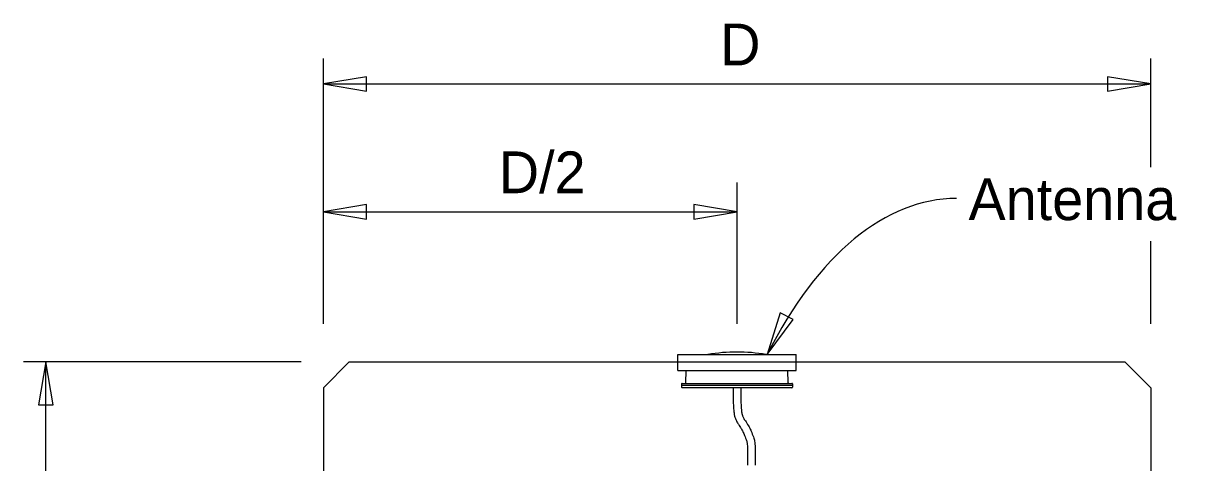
# Model space of a CAD drawing. Extents: x 0 to 36.1, y -3.7 to 15.
# Drawn here: x 1.568 to 4.42, y 8.036 to 9.096 of the extents above; entities that cross this region are included whole.
import ezdxf

# ---------------------------------------------------------------- set-up
doc = ezdxf.new("R2010")
doc.units = 0
for name, color, linetype in [('Dimension', 7, 'Continuous'), ('Leader', 7, 'Continuous'), ('Miscellaneous', 7, 'Continuous'), ('PileConc', 7, 'Continuous'), ('TextStructures', 7, 'Continuous')]:
    doc.layers.add(name, color=color, linetype=linetype)

msp = doc.modelspace()

# ---------------------------------------------------------------- linework, layer by layer
at = {"layer": 'Dimension'}
for p, q in [((2.293, 8.3704), (2.293, 9.0116)), ((4.293, 8.7487), (4.293, 9.0116)), ((2.293, 8.9498), (4.293, 8.9498)), ((3.293, 8.3704), (3.293, 8.7119)), ((2.293, 8.641), (3.293, 8.641)), ((4.293, 8.3704), (4.293, 8.5702)), ((2.2394, 8.2786), (1.5682, 8.2786)), ((1.6218, 6.2786), (1.6218, 8.2786))]:
    msp.add_line(p, q, dxfattribs=at)
for points in [[(2.293, 8.9498), (2.3972, 8.9321), (2.3972, 8.9674)], [(4.293, 8.9498), (4.1889, 8.9674), (4.1889, 8.9321)], [(2.293, 8.641), (2.3972, 8.6233), (2.3972, 8.6586)], [(3.293, 8.641), (3.1889, 8.6586), (3.1889, 8.6233)], [(3.3658, 8.2961), (3.4285, 8.3811), (3.397, 8.397)], [(1.6218, 8.2786), (1.6042, 8.1745), (1.6395, 8.1745)]]:
    msp.add_lwpolyline(points, close=True, dxfattribs=at)
at = {"layer": 'Leader'}
msp.add_ellipse((3.8235, 7.3647), major_axis=(0, -1.3086), ratio=0.497877, start_param=3.141593, end_param=3.920397, dxfattribs=at)
msp.add_spline([(4.7543, 8.0608), (4.6955, 8.0608), (4.6085, 8.0412), (4.5454, 7.9672), (4.528, 7.8301), (4.5389, 7.7126), (4.491, 7.6017), (4.4083, 7.5603), (4.3343, 7.5516), (4.1994, 7.5821), (4.0906, 7.6474), (4.062, 7.6683)], degree=3, dxfattribs=at)
at = {"layer": 'Miscellaneous'}
for p, q in [((3.1499, 8.2961), (3.1915, 8.2961)), ((3.1499, 8.2786), (3.1499, 8.2961)), ((3.1499, 8.2578), (3.1499, 8.2786)), ((3.1499, 8.2786), (3.1915, 8.2786)), ((3.1915, 8.2961), (3.3946, 8.2961)), ((3.1915, 8.2786), (3.3946, 8.2786)), ((3.2228, 8.2962), (3.2228, 8.2961)), ((3.3633, 8.2962), (3.3633, 8.2961)), ((3.3946, 8.2961), (3.4362, 8.2961)), ((3.3946, 8.2786), (3.4362, 8.2786)), ((3.4362, 8.2786), (3.4362, 8.2961)), ((3.4362, 8.2578), (3.4362, 8.2786)), ((3.1499, 8.2578), (3.1915, 8.2578)), ((3.1693, 8.2277), (3.1701, 8.2578)), ((3.1915, 8.2578), (3.3946, 8.2578)), ((3.3946, 8.2578), (3.4362, 8.2578)), ((3.4167, 8.2277), (3.416, 8.2578)), ((3.159, 8.2253), (3.1589, 8.2213)), ((3.1915, 8.2213), (3.1589, 8.2213)), ((3.1589, 8.2213), (3.159, 8.2173)), ((3.1603, 8.2265), (3.1915, 8.2265)), ((3.1915, 8.2161), (3.1603, 8.2161)), ((3.1915, 8.2265), (3.3946, 8.2265)), ((3.3946, 8.2213), (3.1915, 8.2213)), ((3.3946, 8.2161), (3.1915, 8.2161)), ((3.3946, 8.2265), (3.4258, 8.2265)), ((3.4272, 8.2213), (3.3946, 8.2213)), ((3.4258, 8.2161), (3.3946, 8.2161)), ((3.4271, 8.2253), (3.4272, 8.2213)), ((3.4272, 8.2213), (3.4271, 8.2173))]:
    msp.add_line(p, q, dxfattribs=at)
for centre, radius, start, end in [((3.293, 7.8985), 0.4038, 79.9853, 100.0147), ((3.293, 7.8985), 0.4038, 100.0147, 100.0917), ((3.293, 7.8985), 0.4038, 79.9083, 79.9853), ((3.1603, 8.2253), 0.00125, 90, 178.5), ((3.1603, 8.2174), 0.00125, 181.5, 270), ((3.1681, 8.2278), 0.00125, 270, 358.5), ((3.418, 8.2278), 0.00125, 181.5, 270), ((3.4258, 8.2253), 0.00125, 1.5, 90), ((3.4258, 8.2174), 0.00125, 270, 358.5)]:
    msp.add_arc(centre, radius, start, end, dxfattribs=at)
for points in [[(3.2837, 8.2161), (3.2837, 8.2001), (3.2833, 8.1837), (3.2849, 8.1627), (3.2853, 8.1585), (3.2861, 8.1521), (3.2866, 8.1495), (3.2879, 8.1446), (3.2887, 8.1423), (3.2916, 8.1357), (3.2939, 8.1316), (3.2986, 8.1243), (3.3008, 8.1212), (3.3065, 8.1117), (3.3099, 8.1045), (3.3154, 8.0902), (3.3174, 8.0831), (3.3182, 8.0745), (3.3183, 8.0728), (3.3183, 8.0694), (3.3183, 8.067), (3.3183, 8.061), (3.3183, 8.0488), (3.3183, 8.0367), (3.3183, 8.0286)], [(3.3022, 8.2161), (3.3022, 8.1998), (3.3018, 8.1838), (3.3033, 8.1644), (3.3037, 8.1605), (3.3045, 8.1548), (3.3047, 8.1534), (3.3055, 8.1504), (3.3061, 8.1489), (3.3093, 8.1411), (3.3141, 8.135), (3.323, 8.1201), (3.3267, 8.1122), (3.3331, 8.0958), (3.3356, 8.0872), (3.3367, 8.0757), (3.3368, 8.0734), (3.3368, 8.0688), (3.3368, 8.067), (3.3368, 8.061), (3.3368, 8.0488), (3.3368, 8.0367), (3.3368, 8.0286)]]:
    msp.add_open_spline(points, degree=3, dxfattribs=at)
at = {"layer": 'PileConc'}
for p, q in [((2.293, 8.2161), (2.3555, 8.2786)), ((2.3555, 8.2786), (4.2305, 8.2786)), ((4.2305, 8.2786), (4.293, 8.2161)), ((2.293, 8.2161), (2.293, 6.3411)), ((4.293, 8.2161), (4.293, 6.3411))]:
    msp.add_line(p, q, dxfattribs=at)

# ---------------------------------------------------------------- texts
at = {"layer": 'Dimension'}
msp.add_text('Antenna', height=0.1008, dxfattribs=at).set_placement((3.8526, 8.6209))
at = {"layer": 'TextStructures'}
for s, p in [('D', (3.2524, 8.9948)), ('D/2', (2.7171, 8.686))]:
    msp.add_text(s, height=0.1008, dxfattribs=at).set_placement(p)

doc.saveas('drawing.dxf')
